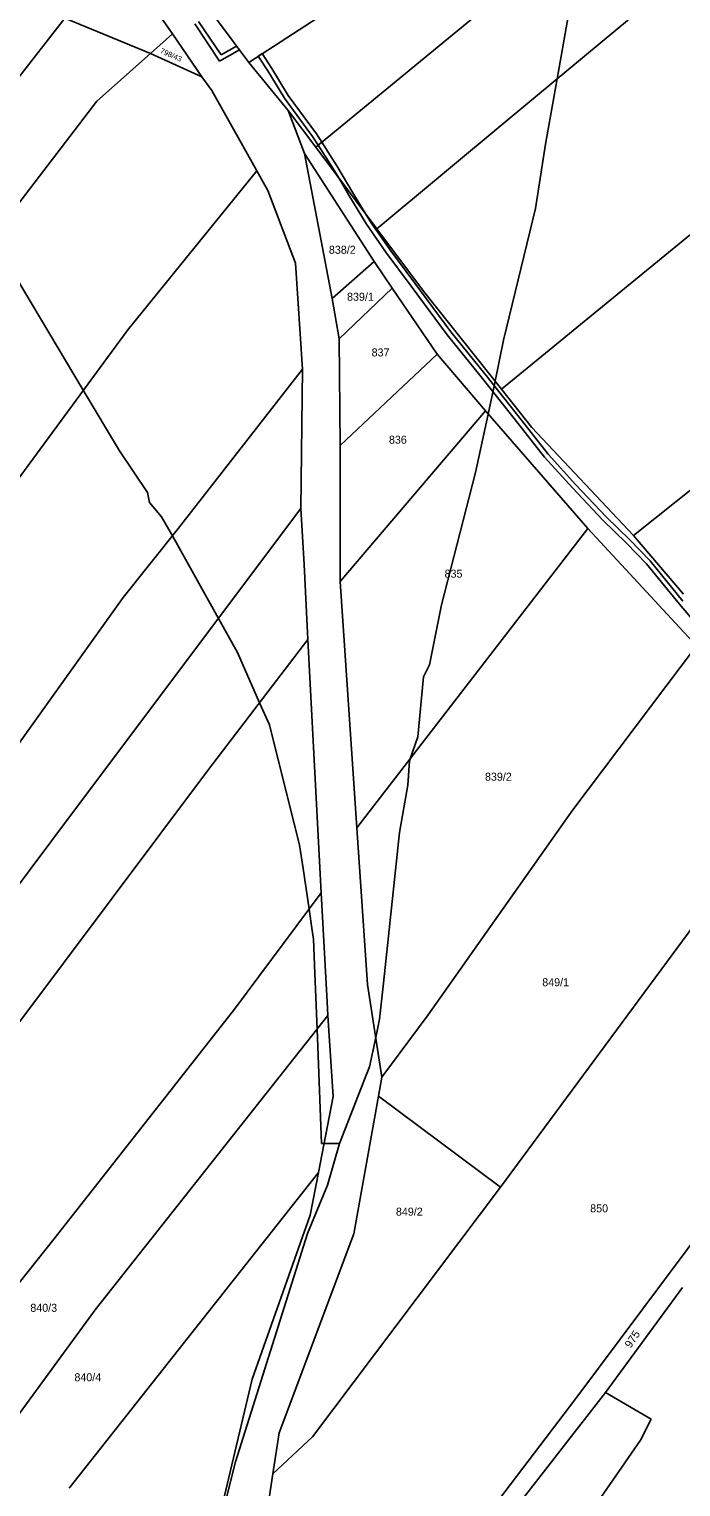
# Model space of a CAD drawing. Extents: x -749173 to -746119, y -1132678 to -1130338.
# Drawn here: x -747634.7 to -747496.1, y -1131633.3 to -1131323.7 of the extents above; entities that cross this region are included whole.
import ezdxf

# ---------------------------------------------------------------- set-up
doc = ezdxf.new("R2010")
doc.units = 0
for name, color, linetype in [('Vrstva 1', 7, 'Continuous'), ('Vrstva 18', 7, 'Continuous'), ('Vrstva 30', 7, 'Continuous'), ('Vrstva 52', 7, 'Continuous'), ('Vrstva 6', 7, 'Continuous')]:
    doc.layers.add(name, color=color, linetype=linetype)

msp = doc.modelspace()

# ---------------------------------------------------------------- linework, layer by layer
at = {"layer": 'Vrstva 1'}
for points in [[(-747613.72, -1131296.16), (-747587.97, -1131330.74)], [(-747604.21, -1131324.68), (-747614.76, -1131309.6)], [(-747627.04, -1131321.32), (-747608.88, -1131328.87)], [(-747597.93, -1131333.8), (-747604.21, -1131324.68)], [(-747608.88, -1131328.87), (-747597.93, -1131333.8)], [(-747579.59, -1131341), (-747587.97, -1131330.74)], [(-747595.82, -1131336.69), (-747597.93, -1131333.8)], [(-747586.28, -1131353.77), (-747595.82, -1131336.69)], [(-747576.14, -1131350.08), (-747579.59, -1131341)], [(-747579.59, -1131341), (-747573.75, -1131348.78)], [(-747576.14, -1131350.08), (-747561.31, -1131373.03)], [(-747570.26, -1131380.88), (-747576.14, -1131350.08)], [(-747573.75, -1131348.78), (-747560.74, -1131366.12)], [(-747583.94, -1131357.96), (-747586.28, -1131353.77)], [(-747578.05, -1131373.41), (-747583.94, -1131357.96)], [(-747560.74, -1131366.12), (-747550.8, -1131379.36)], [(-747576.54, -1131395.88), (-747578.05, -1131373.41)], [(-747561.31, -1131373.03), (-747570.26, -1131380.88)], [(-747561.31, -1131373.03), (-747557.5, -1131378.68)], [(-747570.26, -1131380.88), (-747568.77, -1131389.44)], [(-747557.5, -1131378.68), (-747547.95, -1131392.74)], [(-747550.8, -1131379.36), (-747534.26, -1131400.17)], [(-747568.57, -1131412.15), (-747568.77, -1131389.44)], [(-747547.95, -1131392.74), (-747537.66, -1131404.8)], [(-747576.88, -1131425.52), (-747576.54, -1131395.88)], [(-747534.26, -1131400.17), (-747527.79, -1131408.31)], [(-747537.66, -1131404.8), (-747515.93, -1131429.75)], [(-747527.79, -1131408.31), (-747506.23, -1131431.25)], [(-747568.52, -1131441.05), (-747568.57, -1131412.15)], [(-747576.22, -1131437.4), (-747576.88, -1131425.52)], [(-747515.93, -1131429.75), (-747492.83, -1131454.72)], [(-747506.23, -1131431.25), (-747495.56, -1131443.68)], [(-747575.4, -1131453.35), (-747576.22, -1131437.4)], [(-747564.97, -1131493.37), (-747568.52, -1131441.05)], [(-747573.38, -1131492.36), (-747575.4, -1131453.35)], [(-747572.58, -1131507.18), (-747573.38, -1131492.36)], [(-747562.72, -1131526.64), (-747564.97, -1131493.37)], [(-747571.34, -1131530.28), (-747572.58, -1131507.18)], [(-747559.72, -1131546.32), (-747562.72, -1131526.64)], [(-747571.15, -1131533.2), (-747571.34, -1131530.28)], [(-747570, -1131550.45), (-747571.15, -1131533.2)], [(-747560.43, -1131550.33), (-747559.72, -1131546.32)], [(-747573.17, -1131566.58), (-747570, -1131550.45)], [(-747565.63, -1131579.59), (-747560.43, -1131550.33)], [(-747518.42, -1131614.59), (-747480.55, -1131563.87)], [(-747574.95, -1131575.62), (-747573.17, -1131566.58)], [(-747587.27, -1131610.47), (-747574.95, -1131575.62)], [(-747581.53, -1131621.85), (-747565.63, -1131579.59)], [(-747512.18, -1131613.29), (-747495.81, -1131591.02)], [(-747596.84, -1131650.77), (-747587.27, -1131610.47)], [(-747512.18, -1131613.29), (-747532.53, -1131639.52)], [(-747502.43, -1131618.94), (-747512.18, -1131613.29)], [(-747550, -1131656.02), (-747518.42, -1131614.59)], [(-747504.69, -1131623.44), (-747502.43, -1131618.94)], [(-747582.84, -1131630.56), (-747581.53, -1131621.85)], [(-747559.41, -1131702.48), (-747504.69, -1131623.44)], [(-747584.9, -1131644.26), (-747582.84, -1131630.56)]]:
    msp.add_lwpolyline(points, dxfattribs=at)
at = {"layer": 'Vrstva 30'}
for points in [[(-747594.17, -1131330.47), (-747599.47, -1131322.59)], [(-747598.64, -1131322.03), (-747593.87, -1131329.15)], [(-747589.95, -1131328.08), (-747594.17, -1131330.47)], [(-747593.87, -1131329.15), (-747590.55, -1131327.27)], [(-747590.55, -1131327.27), (-747589.95, -1131328.08)], [(-747585.94, -1131329.43), (-747585.11, -1131328.88)], [(-747585.11, -1131328.88), (-747583.05, -1131332.03)], [(-747583.89, -1131332.57), (-747585.94, -1131329.43)], [(-747583.05, -1131332.03), (-747579.57, -1131337.77)], [(-747580.41, -1131338.33), (-747583.89, -1131332.57)], [(-747579.57, -1131337.77), (-747573.59, -1131345.92)], [(-747574.41, -1131346.5), (-747580.41, -1131338.33)], [(-747573.22, -1131348.35), (-747574.41, -1131346.5)], [(-747573.59, -1131345.92), (-747572.44, -1131347.71)], [(-747572.44, -1131347.71), (-747573.22, -1131348.35)], [(-747573.22, -1131348.35), (-747572.44, -1131347.71)], [(-747570.08, -1131353.23), (-747573.22, -1131348.35)], [(-747572.44, -1131347.71), (-747569.24, -1131352.69)], [(-747568.86, -1131355.29), (-747570.08, -1131353.23)], [(-747569.24, -1131352.69), (-747565.83, -1131358.46)], [(-747566.69, -1131358.98), (-747568.86, -1131355.29)], [(-747563.07, -1131363.01), (-747568.86, -1131355.29)], [(-747568.86, -1131355.29), (-747563.07, -1131363.01)], [(-747562.95, -1131365.14), (-747566.69, -1131358.98)], [(-747565.83, -1131358.46), (-747563.07, -1131363.01)], [(-747563.07, -1131363.01), (-747562.11, -1131364.6)], [(-747558.82, -1131371.08), (-747562.95, -1131365.14)], [(-747562.11, -1131364.6), (-747558, -1131370.5)], [(-747553.48, -1131378.28), (-747558.82, -1131371.08)], [(-747558, -1131370.5), (-747552.68, -1131377.68)], [(-747545.81, -1131388.62), (-747553.48, -1131378.28)], [(-747552.68, -1131377.68), (-747545.03, -1131388)], [(-747538.55, -1131397.56), (-747545.81, -1131388.62)], [(-747545.03, -1131388), (-747537.77, -1131396.94)], [(-747537.77, -1131396.94), (-747530.76, -1131405.78)], [(-747531.54, -1131406.4), (-747538.55, -1131397.56)], [(-747525.1, -1131414.61), (-747531.54, -1131406.4)], [(-747530.76, -1131405.78), (-747524.34, -1131413.97)], [(-747519.17, -1131421.15), (-747525.1, -1131414.61)], [(-747524.34, -1131413.97), (-747518.45, -1131420.47)], [(-747512.75, -1131428), (-747519.17, -1131421.15)], [(-747518.45, -1131420.47), (-747512.04, -1131427.3)], [(-747507.67, -1131432.85), (-747512.75, -1131428)], [(-747512.04, -1131427.3), (-747506.95, -1131432.15)], [(-747503.44, -1131437.29), (-747507.67, -1131432.85)], [(-747506.95, -1131432.15), (-747502.68, -1131436.63)], [(-747496.45, -1131445.81), (-747503.44, -1131437.29)], [(-747502.68, -1131436.63), (-747495.69, -1131445.17)], [(-747489.76, -1131453.68), (-747496.45, -1131445.81)]]:
    msp.add_lwpolyline(points, dxfattribs=at)
at = {"layer": 'Vrstva 52'}
for points in [[(-747568.69, -1131560.37), (-747562.86, -1131545.52), (-747562.31, -1131544.12), (-747561, -1131537.89), (-747560.19, -1131534), (-747559.31, -1131526.37), (-747555.94, -1131494.37), (-747554.19, -1131484.25), (-747553.81, -1131479.12), (-747553.67, -1131478.71), (-747552.06, -1131474), (-747550.81, -1131461.25), (-747549.56, -1131458.75), (-747547, -1131446), (-747539.75, -1131417.87), (-747537.09, -1131405.45), (-747536.37, -1131402.12), (-747535.97, -1131400.16), (-747535.62, -1131398.46), (-747533.81, -1131389.75), (-747527, -1131361.75), (-747524.87, -1131348.12), (-747522.43, -1131334.23), (-747516.7, -1131301.69)], [(-747637.56, -1131376.25), (-747623.14, -1131400.37), (-747615.44, -1131413.25), (-747609.5, -1131422.12), (-747609.06, -1131424.25), (-747606.5, -1131427.25), (-747604.21, -1131431.35), (-747594.42, -1131448.88), (-747590.37, -1131456.12), (-747585.66, -1131466.77), (-747583.56, -1131471.5), (-747577.19, -1131497), (-747576.44, -1131501.99), (-747575.14, -1131510.61), (-747574.54, -1131514.66), (-747574.19, -1131517), (-747573.91, -1131524.26), (-747573.44, -1131536.1), (-747572.5, -1131560.37), (-747571.95, -1131560.37), (-747568.69, -1131560.37)], [(-747593.37, -1131638.12), (-747590.81, -1131628), (-747575.5, -1131579.5), (-747571.25, -1131569.25), (-747568.69, -1131560.37)]]:
    msp.add_lwpolyline(points, dxfattribs=at)
at = {"layer": 'Vrstva 6'}
for points in [[(-747438.82, -1131264.87), (-747532.83, -1131342.86)], [(-747519.29, -1131304), (-747573.75, -1131348.78)], [(-747567.99, -1131317.8), (-747587.97, -1131330.74)], [(-747669.96, -1131376.28), (-747627.04, -1131321.32)], [(-747608.88, -1131328.87), (-747604.21, -1131324.68)], [(-747608.88, -1131328.87), (-747620.26, -1131339)], [(-747620.26, -1131339), (-747658, -1131388.25)], [(-747532.83, -1131342.86), (-747560.74, -1131366.12)], [(-747613.7, -1131387.55), (-747586.28, -1131353.77)], [(-747480.38, -1131356.14), (-747534.26, -1131400.17)], [(-747568.77, -1131389.44), (-747557.5, -1131378.68)], [(-747658.45, -1131448.35), (-747613.7, -1131387.55)], [(-747547.95, -1131392.74), (-747568.57, -1131412.15)], [(-747576.54, -1131395.88), (-747602.9, -1131429.72)], [(-747537.66, -1131404.8), (-747568.52, -1131441.05)], [(-747474.44, -1131405.95), (-747506.23, -1131431.25)], [(-747625.65, -1131490.48), (-747576.88, -1131425.52)], [(-747602.9, -1131429.72), (-747614.66, -1131444.39)], [(-747515.93, -1131429.75), (-747564.97, -1131493.37)], [(-747614.66, -1131444.39), (-747654.43, -1131499.96)], [(-747596.53, -1131480.99), (-747575.4, -1131453.35)], [(-747492.83, -1131454.72), (-747519.12, -1131489.53)], [(-747637.49, -1131535.62), (-747596.53, -1131480.99)], [(-747469.89, -1131482.38), (-747534.47, -1131569.66)], [(-747519.12, -1131489.53), (-747549.84, -1131533.09)], [(-747669.23, -1131548.64), (-747625.65, -1131490.48)], [(-747572.58, -1131507.18), (-747591, -1131531.84)], [(-747591, -1131531.84), (-747629.09, -1131580.38)], [(-747571.15, -1131533.2), (-747620.64, -1131595.74)], [(-747549.84, -1131533.09), (-747559.72, -1131546.32)], [(-747534.47, -1131569.66), (-747560.43, -1131550.33)], [(-747626.14, -1131633.64), (-747573.17, -1131566.58)], [(-747534.47, -1131569.66), (-747574.44, -1131622.7)], [(-747629.09, -1131580.38), (-747664.74, -1131625.11)], [(-747620.64, -1131595.74), (-747646.64, -1131631.19)], [(-747574.44, -1131622.7), (-747582.84, -1131630.56)]]:
    msp.add_lwpolyline(points, dxfattribs=at)

# ---------------------------------------------------------------- texts
at = {"layer": 'Vrstva 18'}
for s, height, rotation, p in [('798/43', 1.14, 336.1048, (-747606.93, -1131328.69)), ('975', 1.7, 56.0802, (-747506.8, -1131604.01))]:
    msp.add_text(s, height=height, rotation=rotation, dxfattribs=at).set_placement(p)
for s, p in [('838/2', (-747570.94, -1131371.4)), ('839/1', (-747567.08, -1131381.38)), ('837', (-747561.86, -1131393.21)), ('836', (-747558.18, -1131411.74)), ('835', (-747546.35, -1131440.21)), ('839/2', (-747537.76, -1131483.34)), ('849/1', (-747525.59, -1131527)), ('850', (-747515.4, -1131575.03)), ('849/2', (-747556.69, -1131575.73)), ('840/3', (-747634.4, -1131596.16)), ('840/4', (-747625.03, -1131610.91))]:
    msp.add_text(s, height=1.7, dxfattribs=at).set_placement(p)

doc.saveas('drawing.dxf')
